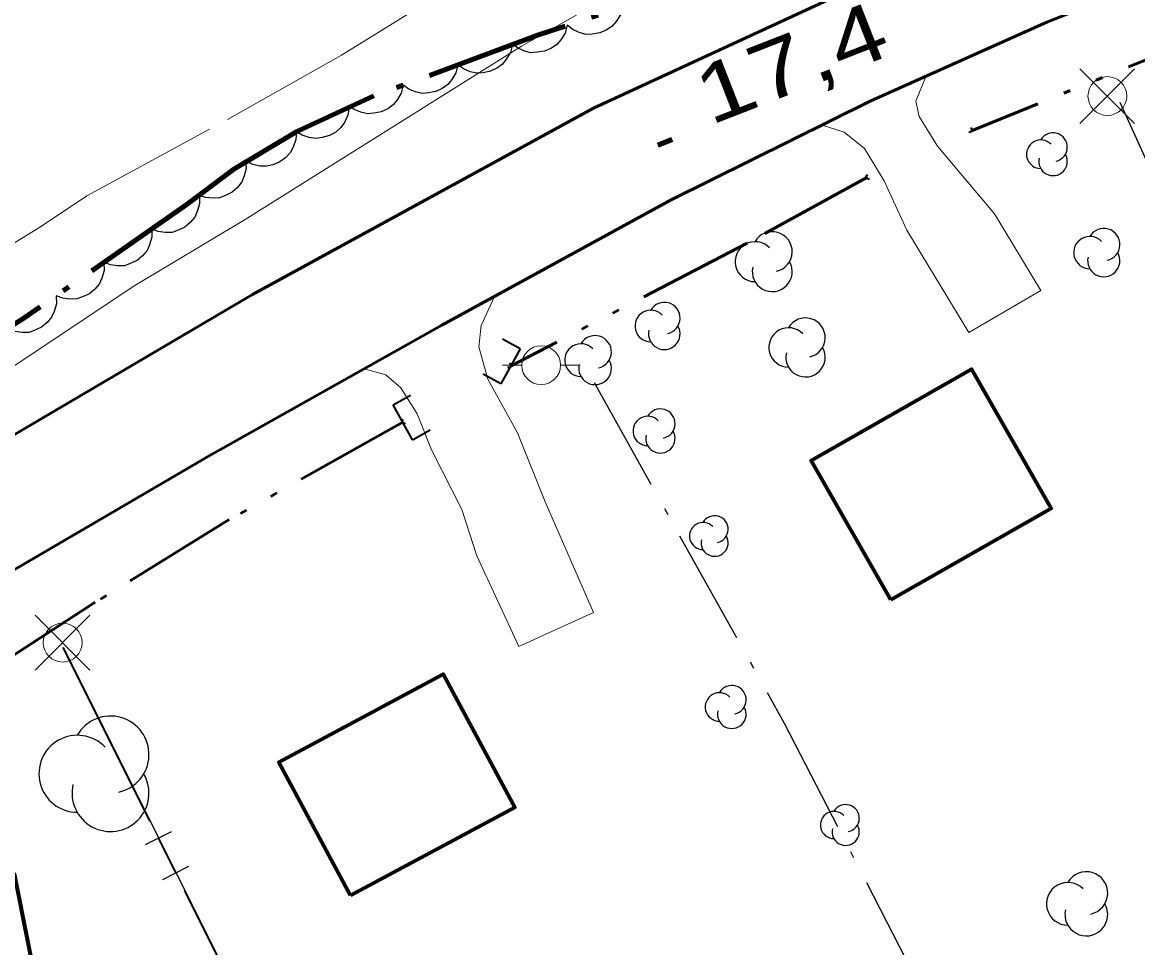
# Model space of a CAD drawing. Extents: x 386081 to 389416, y 5130568 to 5134082.
# Drawn here: x 387664.9 to 387722.3, y 5132372.2 to 5132419.9 of the extents above; entities that cross this region are included whole.
import ezdxf

# ---------------------------------------------------------------- set-up
doc = ezdxf.new("R2010")
doc.units = 0
doc.header["$LTSCALE"] = 1.2
for name, pattern in [('DASH_DOUBLE_DOT', [9.2, 5, -1.2, 0.3, -1.2, 0.3, -1.2]), ('DOT_DASHED', [7.7, 5, -1.2, 0.3, -1.2]), ('LONG_DASHED', [7.5, 6, -1.5])]:
    doc.linetypes.add(name, pattern=pattern)
for name, color, linetype, lineweight in [('19', 7, 'Continuous', 13), ('2', 7, 'Continuous', 13), ('21', 7, 'LONG_DASHED', 35), ('26', 7, 'Continuous', 35), ('3', 7, 'Continuous', 140), ('31', 7, 'Continuous', 70), ('36', 7, 'Continuous', 13), ('37', 7, 'Continuous', 13), ('4', 7, 'DASH_DOUBLE_DOT', 53), ('41', 7, 'DOT_DASHED', 25), ('44', 7, 'Continuous', 25)]:
    doc.layers.add(name, color=color, linetype=linetype, lineweight=lineweight)

msp = doc.modelspace()

# ---------------------------------------------------------------- linework, layer by layer
at = {"layer": '19'}
for points in [[(387706.09, 5132414.63), (387707.22, 5132414.26), (387708.27, 5132413.42), (387709.27, 5132411.76), (387710.45, 5132409.21), (387713.64, 5132403.95), (387717.34, 5132406.11), (387714.96, 5132410.05), (387712.03, 5132413.54), (387711.08, 5132415.08), (387710.91, 5132415.87), (387711.44, 5132417.16)], [(387682.48, 5132402.07), (387683.61, 5132401.76), (387684.37, 5132401.09), (387685.21, 5132399.76), (387685.95, 5132397.9), (387687.51, 5132394.82), (387688.29, 5132392.44), (387690.45, 5132387.76), (387694.3, 5132389.51), (387691.81, 5132395.21), (387690.38, 5132398.78), (387688.85, 5132401.54), (387688.39, 5132403.2), (387688.52, 5132404.3), (387689.2, 5132405.8)]]:
    msp.add_lwpolyline(points, dxfattribs=at)
at = {"layer": '2', "linetype": 'LONG_DASHED'}
msp.add_lwpolyline([(387646.04, 5132395.15), (387652.31, 5132399.77), (387656.69, 5132402.85), (387660.07, 5132405.69), (387663.19, 5132407.78), (387665.82, 5132409.38), (387668.2, 5132410.98), (387675.44, 5132414.92), (387681.32, 5132418.24), (387685.32, 5132420.71), (387693.32, 5132425.39), (387696.95, 5132427.48), (387699.7, 5132428.96), (387703.19, 5132430.43), (387712.56, 5132434), (387723.8, 5132437.93), (387728.3, 5132439.41), (387749.79, 5132447.28), (387763.29, 5132451.71), (387765.79, 5132452.44), (387774.66, 5132454.78)], dxfattribs=at)
at = {"layer": '2'}
msp.add_lwpolyline([(387595.78, 5132354.61), (387596.25, 5132355.95), (387598.89, 5132358.28), (387632.06, 5132382.54), (387636.36, 5132385.22), (387647.69, 5132391.91), (387663.55, 5132401.63), (387670.59, 5132406.32), (387676.35, 5132409.76), (387690.6, 5132418.7), (387697.88, 5132422.84), (387700.46, 5132423.92), (387709.45, 5132427.98), (387714.62, 5132429.92), (387724.45, 5132433.25), (387748.22, 5132441.01), (387752.95, 5132442.88), (387758.29, 5132444.63), (387774.49, 5132449.59), (387777.24, 5132450.08), (387781.76, 5132450.54)], dxfattribs=at)
at = {"layer": '21', "linetype": 'Continuous', "lineweight": 53}
for points in [[(387557.81, 5132325.38), (387576.23, 5132338.46), (387587.5, 5132346.55), (387599.94, 5132355.62), (387622.38, 5132371.51), (387636.53, 5132381.25), (387650.59, 5132390.2), (387662.07, 5132397.28), (387676.74, 5132405.9), (387694.3, 5132415.51), (387711.08, 5132423.26), (387726, 5132429.44), (387744.28, 5132435.55), (387768.17, 5132442.46), (387774.39, 5132443.7)], [(387775.71, 5132438.07), (387771.14, 5132437.34), (387766.06, 5132436.17), (387755.74, 5132433.22), (387743.87, 5132429.41), (387734.89, 5132426.38), (387725.2, 5132422.94), (387717.65, 5132419.94), (387708.55, 5132415.86), (387698.31, 5132410.78), (387686.48, 5132404.32), (387674.51, 5132397.59), (387661.05, 5132389.74)]]:
    msp.add_lwpolyline(points, dxfattribs=at)
at = {"layer": '26'}
for p, q in [((387713.73, 5132414.25), (387713.64, 5132414.29)), ((387713.73, 5132414.25), (387713.64, 5132414.29)), ((387713.81, 5132414.43), (387713.72, 5132414.47)), ((387713.81, 5132414.43), (387713.72, 5132414.47)), ((387713.81, 5132414.43), (387713.73, 5132414.25)), ((387713.81, 5132414.43), (387713.73, 5132414.25)), ((387708.35, 5132412.02), (387708.44, 5132412.06)), ((387708.35, 5132412.02), (387708.44, 5132412.06)), ((387708.43, 5132411.84), (387708.35, 5132412.02)), ((387708.43, 5132411.84), (387708.35, 5132412.02)), ((387708.43, 5132411.84), (387708.52, 5132411.88)), ((387708.43, 5132411.84), (387708.52, 5132411.88)), ((387690.52, 5132403.1), (387689.62, 5132403.6)), ((387690.52, 5132403.1), (387689.52, 5132401.3)), ((387689.97, 5132402.11), (387689.88, 5132402.16)), ((387690.07, 5132402.29), (387689.97, 5132402.11)), ((387690.07, 5132402.29), (387689.98, 5132402.34)), ((387689.52, 5132401.3), (387688.62, 5132401.8)), ((387683.98, 5132400.22), (387684.88, 5132400.72)), ((387684.98, 5132398.42), (387683.98, 5132400.22)), ((387684.43, 5132399.41), (387684.52, 5132399.46)), ((387684.53, 5132399.23), (387684.43, 5132399.41)), ((387684.53, 5132399.23), (387684.62, 5132399.28)), ((387684.98, 5132398.42), (387685.88, 5132398.92))]:
    msp.add_line(p, q, dxfattribs=at)
at = {"layer": '3'}
msp.add_line((387697.62, 5132413.59), (387698.36, 5132413.88), dxfattribs=at)
at = {"layer": '31'}
for points in [[(387709.62, 5132390.16), (387705.52, 5132397.34), (387713.78, 5132402.05), (387717.88, 5132394.87)], [(387681.78, 5132374.93), (387678.09, 5132381.8), (387686.55, 5132386.34), (387690.24, 5132379.46)], [(387655.52, 5132362.88), (387653.34, 5132373.86), (387664.46, 5132376.05), (387666.64, 5132365.09)]]:
    msp.add_lwpolyline(points, close=True, dxfattribs=at)
at = {"layer": '36'}
for p, q in [((387722.18, 5132414.71), (387719.36, 5132417.53)), ((387719.36, 5132414.71), (387722.18, 5132417.53)), ((387689.61, 5132402.26), (387690.61, 5132402.26)), ((387693.61, 5132402.26), (387692.61, 5132402.26)), ((387668.36, 5132386.55), (387665.54, 5132389.37)), ((387665.54, 5132386.55), (387668.36, 5132389.37))]:
    msp.add_line(p, q, dxfattribs=at)
for centre in [(387720.774, 5132416.125), (387691.604, 5132402.26), (387666.954, 5132387.965)]:
    msp.add_circle(centre, 1, dxfattribs=at)
at = {"layer": '37', "lineweight": 25}
for p, q in [((387666.94, 5132387.71), (387671.42, 5132378.77)), ((387666.98, 5132387.73), (387677.94, 5132365.86)), ((387672.54, 5132378.21), (387671.2, 5132377.54)), ((387671.87, 5132377.88), (387672.76, 5132376.09)), ((387673.43, 5132376.42), (387672.09, 5132375.75)), ((387673.21, 5132375.19), (387677.69, 5132366.25))]:
    msp.add_line(p, q, dxfattribs=at)
at = {"layer": '4'}
msp.add_line((387727.42, 5132419.88), (387713.77, 5132414.34), dxfattribs=at)
for points in [[(387708.39, 5132411.93), (387702.21, 5132408.55), (387690.02, 5132402.2)], [(387684.48, 5132399.32), (387675.54, 5132394.3), (387668.63, 5132390.04), (387661.36, 5132385.33)]]:
    msp.add_lwpolyline(points, dxfattribs=at)
at = {"layer": '41'}
for points in [[(387721.41, 5132415.81), (387725.61, 5132406.57), (387732.59, 5132393.35), (387741.11, 5132375.16)], [(387694.33, 5132401.37), (387698.74, 5132393.46), (387704.13, 5132383.82), (387717.31, 5132358.2)]]:
    msp.add_lwpolyline(points, dxfattribs=at)
at = {"layer": '44', "linetype": 'DOT_DASHED', "lineweight": 90}
msp.add_lwpolyline([(387775.88, 5132444.91), (387769.76, 5132444.69), (387765.52, 5132444.93), (387758.05, 5132444.92), (387757.02, 5132444.57), (387755.45, 5132443.59), (387753.1, 5132441.67), (387748.79, 5132438.73), (387746.88, 5132437.8), (387741.09, 5132435.41), (387732.18, 5132432.05), (387722.1, 5132428.62), (387716.52, 5132427.09), (387701.61, 5132422.63), (387691.47, 5132419.28), (387682.99, 5132416.13), (387679.01, 5132414.3), (387675.77, 5132412.36), (387673.37, 5132410.55), (387664.96, 5132404.68), (387659.44, 5132401.19)], dxfattribs=at)
at = {"layer": '44'}
for points in [[(387695.8, 5132420.71), (387695.69, 5132420.31), (387695.47, 5132419.97), (387695.25, 5132419.71), (387694.96, 5132419.52), (387694.62, 5132419.38), (387694.24, 5132419.32), (387693.91, 5132419.3), (387693.57, 5132419.4), (387693.24, 5132419.55), (387692.95, 5132419.77)], [(387692.95, 5132419.77), (387692.84, 5132419.37), (387692.62, 5132419.02), (387692.4, 5132418.77), (387692.11, 5132418.58), (387691.77, 5132418.44), (387691.39, 5132418.38), (387691.06, 5132418.36), (387690.72, 5132418.45), (387690.39, 5132418.61), (387690.1, 5132418.83)], [(387690.12, 5132418.78), (387690.02, 5132418.37), (387689.81, 5132418.02), (387689.61, 5132417.76), (387689.32, 5132417.56), (387688.99, 5132417.4), (387688.61, 5132417.33), (387688.29, 5132417.3), (387687.94, 5132417.38), (387687.6, 5132417.52), (387687.31, 5132417.73)], [(387687.31, 5132417.73), (387687.21, 5132417.33), (387687, 5132416.98), (387686.8, 5132416.72), (387686.51, 5132416.52), (387686.18, 5132416.36), (387685.8, 5132416.29), (387685.47, 5132416.26), (387685.13, 5132416.34), (387684.79, 5132416.48), (387684.49, 5132416.69)], [(387684.49, 5132416.69), (387684.4, 5132416.28), (387684.19, 5132415.93), (387683.98, 5132415.67), (387683.7, 5132415.47), (387683.36, 5132415.31), (387682.99, 5132415.24), (387682.66, 5132415.21), (387682.32, 5132415.29), (387681.98, 5132415.44), (387681.68, 5132415.64)], [(387681.72, 5132415.55), (387681.65, 5132415.14), (387681.47, 5132414.77), (387681.29, 5132414.5), (387681.02, 5132414.27), (387680.7, 5132414.09), (387680.33, 5132413.99), (387680.01, 5132413.94), (387679.66, 5132413.99), (387679.3, 5132414.11), (387679, 5132414.29)], [(387679, 5132414.29), (387678.97, 5132413.88), (387678.83, 5132413.49), (387678.68, 5132413.2), (387678.44, 5132412.95), (387678.14, 5132412.73), (387677.78, 5132412.59), (387677.46, 5132412.51), (387677.11, 5132412.52), (387676.75, 5132412.6), (387676.42, 5132412.75)], [(387676.38, 5132412.82), (387676.4, 5132412.4), (387676.3, 5132412.01), (387676.18, 5132411.7), (387675.96, 5132411.42), (387675.69, 5132411.18), (387675.35, 5132411), (387675.04, 5132410.88), (387674.69, 5132410.86), (387674.32, 5132410.9), (387673.98, 5132411.01)], [(387674, 5132410.99), (387674.01, 5132410.57), (387673.89, 5132410.18), (387673.76, 5132409.88), (387673.53, 5132409.61), (387673.25, 5132409.37), (387672.9, 5132409.21), (387672.6, 5132409.1), (387672.24, 5132409.09), (387671.88, 5132409.14), (387671.54, 5132409.27)], [(387671.54, 5132409.27), (387671.55, 5132408.85), (387671.43, 5132408.46), (387671.3, 5132408.16), (387671.07, 5132407.89), (387670.79, 5132407.66), (387670.44, 5132407.49), (387670.14, 5132407.38), (387669.78, 5132407.38), (387669.42, 5132407.43), (387669.08, 5132407.56)], [(387669.08, 5132407.56), (387669.09, 5132407.14), (387668.97, 5132406.75), (387668.84, 5132406.44), (387668.61, 5132406.18), (387668.33, 5132405.94), (387667.98, 5132405.78), (387667.68, 5132405.67), (387667.32, 5132405.66), (387666.96, 5132405.71), (387666.62, 5132405.84)], [(387666.62, 5132405.84), (387666.63, 5132405.42), (387666.51, 5132405.03), (387666.38, 5132404.73), (387666.15, 5132404.46), (387665.87, 5132404.22), (387665.52, 5132404.06), (387665.22, 5132403.95), (387664.86, 5132403.94), (387664.5, 5132403.99), (387664.16, 5132404.12)]]:
    msp.add_lwpolyline(points, dxfattribs=at)
for centre, radius, start, end in [((387717.977, 5132413.494), 0.735, 282.26917, 149.72626), ((387717.345, 5132413.127), 0.735, 44.11537, 269.80396), ((387717.977, 5132412.759), 0.735, 166.93686, 29.62122), ((387703.51, 5132408.108), 1.029, 282.26917, 149.72626), ((387719.872, 5132408.059), 0.832, 44.11537, 269.80396), ((387720.588, 5132408.475), 0.832, 282.26917, 149.72626), ((387702.625, 5132407.593), 1.029, 44.11537, 269.80396), ((387720.588, 5132407.643), 0.832, 166.93686, 29.62122), ((387703.51, 5132407.079), 1.029, 166.93686, 29.62122), ((387697.949, 5132404.684), 0.811, 282.26917, 149.72626), ((387697.251, 5132404.278), 0.811, 44.11537, 269.80396), ((387697.949, 5132403.873), 0.811, 166.93686, 29.62122), ((387704.351, 5132403.173), 1.014, 44.11537, 269.80396), ((387705.224, 5132403.68), 1.014, 282.26917, 149.72626), ((387694.382, 5132402.94), 0.842, 282.26917, 149.72626), ((387693.657, 5132402.519), 0.842, 44.11537, 269.80396), ((387705.224, 5132402.666), 1.014, 166.93686, 29.62122), ((387694.382, 5132402.098), 0.842, 166.93686, 29.62122), ((387697.095, 5132398.867), 0.758, 44.11537, 269.80396), ((387697.747, 5132399.246), 0.758, 282.26917, 149.72626), ((387697.747, 5132398.488), 0.758, 166.93686, 29.62122), ((387700.541, 5132393.804), 0.697, 282.26917, 149.72626), ((387699.942, 5132393.456), 0.697, 44.11537, 269.80396), ((387700.541, 5132393.107), 0.697, 166.93686, 29.62122), ((387700.794, 5132384.647), 0.738, 44.11537, 269.80396), ((387700.794, 5132384.647), 0.738, 44.11537, 269.80396), ((387701.428, 5132385.016), 0.738, 282.26917, 149.72626), ((387701.428, 5132385.016), 0.738, 282.26917, 149.72626), ((387701.428, 5132384.278), 0.738, 166.93686, 29.62122), ((387701.428, 5132384.278), 0.738, 166.93686, 29.62122), ((387669.418, 5132382.197), 1.983, 282.26917, 149.72626), ((387667.713, 5132381.205), 1.983, 44.11537, 269.80396), ((387669.418, 5132380.213), 1.983, 166.93686, 29.62122), ((387707.293, 5132378.916), 0.701, 282.26917, 149.72626), ((387707.293, 5132378.916), 0.701, 282.26917, 149.72626), ((387706.69, 5132378.566), 0.701, 44.11537, 269.80396), ((387706.69, 5132378.566), 0.701, 44.11537, 269.80396), ((387707.293, 5132378.215), 0.701, 166.93686, 29.62122), ((387707.293, 5132378.215), 0.701, 166.93686, 29.62122), ((387719.69, 5132375.056), 1.102, 282.26917, 149.72626), ((387718.743, 5132374.505), 1.102, 44.11537, 269.80396), ((387719.69, 5132373.954), 1.102, 166.93686, 29.62122)]:
    msp.add_arc(centre, radius, start, end, dxfattribs=at)

# ---------------------------------------------------------------- texts
at = {"layer": '3', "width": 1.3}
msp.add_text('17,4   ', height=3, rotation=21.353, dxfattribs=at).set_placement((387700.31, 5132414.6))

doc.saveas('drawing.dxf')
